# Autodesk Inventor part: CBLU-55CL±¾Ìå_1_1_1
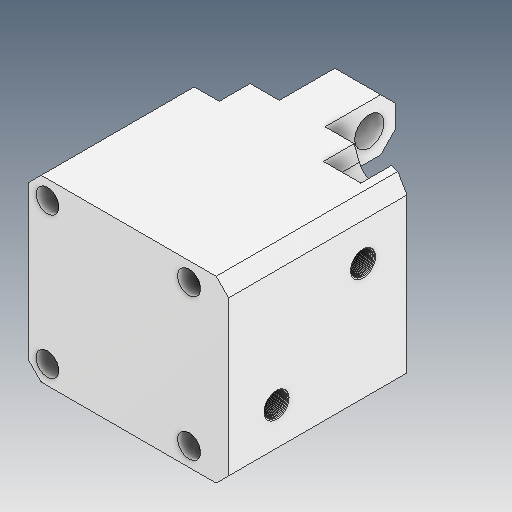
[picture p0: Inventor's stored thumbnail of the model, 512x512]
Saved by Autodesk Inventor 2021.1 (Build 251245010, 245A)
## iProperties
Created: 2021-05
Part Number: CBLU-55CL±¾Ìå_1_1_1
Material: Ogólny
Document SubType Name: Modeling
Designer: user
Density: 1 g/cm^3
Appearance: Domyślna
Author: user
Revision Number: ÈÎºÎ
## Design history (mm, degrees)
feature "ÊäÈë1"
feature "ÊäÈë2"
node "Bryła1"
node "Bryła2"
